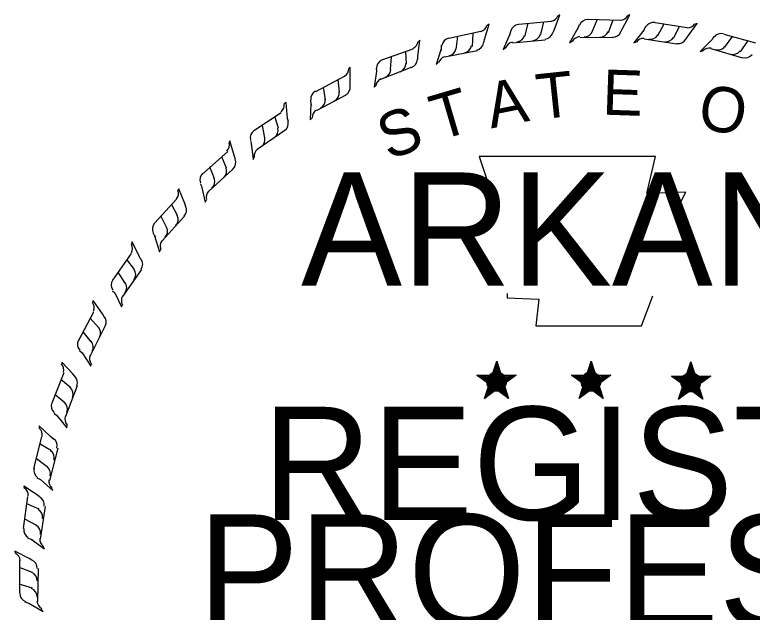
# Model space of a CAD drawing. Extents: x -1063117.8 to -1063083.7, y -253323.4 to -253301.6.
# Drawn here: x -1063093.123 to -1063091.9, y -253321.122 to -253320.131 of the extents above; entities that cross this region are included whole.
import ezdxf

# ---------------------------------------------------------------- set-up
doc = ezdxf.new("R2010")
doc.units = 0
doc.layers.add('Stamp-ChrisC', color=7, linetype='Continuous')

msp = doc.modelspace()

# ---------------------------------------------------------------- linework, layer by layer
at = {"layer": 'Stamp-ChrisC'}
for p, q in [((-1063092.2284, -253320.1569), (-1063092.2194, -253320.1314)), ((-1063092.2194, -253320.1314), (-1063092.2224, -253320.1337)), ((-1063092.1159, -253320.1554), (-1063092.1032, -253320.1314)), ((-1063092.1032, -253320.1314), (-1063092.1062, -253320.1329)), ((-1063092.2869, -253320.1472), (-1063092.2329, -253320.1419)), ((-1063092.2509, -253320.1644), (-1063092.2457, -253320.1434)), ((-1063092.1722, -253320.1389), (-1063092.1182, -253320.1404)), ((-1063092.1654, -253320.1599), (-1063092.1572, -253320.1397)), ((-1063092.1384, -253320.1607), (-1063092.1309, -253320.1397)), ((-1063092.3439, -253320.1727), (-1063092.3364, -253320.1472)), ((-1063092.3364, -253320.1472), (-1063092.3394, -253320.1494)), ((-1063092.2772, -253320.1674), (-1063092.2719, -253320.1457)), ((-1063092.1894, -253320.1539), (-1063092.2029, -253320.1779)), ((-1063092.1894, -253320.1539), (-1063092.1902, -253320.1562)), ((-1063092.1872, -253320.1479), (-1063092.1894, -253320.1539)), ((-1063092.1182, -253320.1599), (-1063092.1159, -253320.1554)), ((-1063092.0769, -253320.1509), (-1063092.0799, -253320.1569)), ((-1063092.0612, -253320.1442), (-1063092.0079, -253320.1524)), ((-1063092.0567, -253320.1659), (-1063092.0462, -253320.1464)), ((-1063092.0304, -253320.1704), (-1063092.0207, -253320.1509)), ((-1063092.0072, -253320.1682), (-1063091.9914, -253320.1457)), ((-1063091.9914, -253320.1457), (-1063091.9944, -253320.1472)), ((-1063092.4032, -253320.1704), (-1063092.3499, -253320.1584)), ((-1063092.3912, -253320.1892), (-1063092.3882, -253320.1667)), ((-1063092.3642, -253320.1839), (-1063092.3627, -253320.1622)), ((-1063092.3019, -253320.1637), (-1063092.3132, -253320.1892)), ((-1063092.3019, -253320.1637), (-1063092.3027, -253320.1659)), ((-1063092.3004, -253320.1577), (-1063092.3019, -253320.1637)), ((-1063092.2307, -253320.1614), (-1063092.2284, -253320.1569)), ((-1063092.0799, -253320.1569), (-1063092.0964, -253320.1779)), ((-1063092.0799, -253320.1569), (-1063092.0807, -253320.1584)), ((-1063092.0102, -253320.1719), (-1063092.0072, -253320.1682)), ((-1063091.9637, -253320.1674), (-1063091.9667, -253320.1727)), ((-1063091.9472, -253320.1637), (-1063091.8947, -253320.1779)), ((-1063091.9457, -253320.1854), (-1063091.9329, -253320.1674)), ((-1063092.4549, -253320.2004), (-1063092.4512, -253320.1734)), ((-1063092.4512, -253320.1734), (-1063092.4534, -253320.1764)), ((-1063092.3454, -253320.1779), (-1063092.3439, -253320.1727)), ((-1063092.2434, -253320.1734), (-1063092.2974, -253320.1787)), ((-1063092.2029, -253320.1779), (-1063092.1984, -253320.1749)), ((-1063092.1309, -253320.1697), (-1063092.1857, -253320.1689)), ((-1063092.0964, -253320.1779), (-1063092.0919, -253320.1757)), ((-1063092.0252, -253320.1802), (-1063092.0792, -253320.1719)), ((-1063091.9667, -253320.1727), (-1063091.9862, -253320.1922)), ((-1063091.9667, -253320.1727), (-1063091.9682, -253320.1742)), ((-1063091.9194, -253320.1929), (-1063091.9067, -253320.1742)), ((-1063092.5142, -253320.2064), (-1063092.4624, -253320.1877)), ((-1063092.4737, -253320.2132), (-1063092.4744, -253320.1922)), ((-1063092.4159, -253320.1877), (-1063092.4242, -253320.2139)), ((-1063092.4159, -253320.1817), (-1063092.4159, -253320.1877)), ((-1063092.4159, -253320.1877), (-1063092.4159, -253320.1907)), ((-1063092.3559, -253320.1914), (-1063092.4099, -253320.2019)), ((-1063092.3132, -253320.1892), (-1063092.3087, -253320.1854)), ((-1063091.9862, -253320.1922), (-1063091.9809, -253320.1907)), ((-1063091.9157, -253320.2034), (-1063091.9682, -253320.1877)), ((-1063092.4999, -253320.2222), (-1063092.4984, -253320.2012)), ((-1063092.4549, -253320.2057), (-1063092.4549, -253320.2004)), ((-1063092.4242, -253320.2139), (-1063092.4204, -253320.2102)), ((-1063092.5667, -253320.2184), (-1063092.5689, -253320.2207)), ((-1063092.5667, -253320.2447), (-1063092.5667, -253320.2184)), ((-1063092.5232, -253320.2252), (-1063092.5269, -253320.2514)), ((-1063092.5239, -253320.2199), (-1063092.5232, -253320.2252)), ((-1063092.5232, -253320.2252), (-1063092.5239, -253320.2282)), ((-1063092.4647, -253320.2184), (-1063092.5164, -253320.2387)), ((-1063092.6237, -253320.2589), (-1063092.5764, -253320.2334)), ((-1063092.5847, -253320.2597), (-1063092.5869, -253320.2387)), ((-1063092.6079, -253320.2724), (-1063092.6109, -253320.2514)), ((-1063092.5667, -253320.2499), (-1063092.5667, -253320.2447)), ((-1063092.5269, -253320.2514), (-1063092.5239, -253320.2484)), ((-1063092.5742, -253320.2649), (-1063092.6222, -253320.2904)), ((-1063092.6732, -253320.2769), (-1063092.6762, -253320.2792)), ((-1063092.6709, -253320.3032), (-1063092.6732, -253320.2769)), ((-1063092.6327, -253320.2732), (-1063092.6319, -253320.2792)), ((-1063092.6319, -253320.2792), (-1063092.6334, -253320.3054)), ((-1063092.6319, -253320.2792), (-1063092.6312, -253320.2814)), ((-1063092.7264, -253320.3234), (-1063092.6814, -253320.2934)), ((-1063092.6859, -253320.3197), (-1063092.6919, -253320.3002)), ((-1063092.6334, -253320.3054), (-1063092.6297, -253320.3024)), ((-1063092.7084, -253320.3354), (-1063092.7122, -253320.3152)), ((-1063092.6694, -253320.3084), (-1063092.6709, -253320.3032)), ((-1063092.6754, -253320.3234), (-1063092.7212, -253320.3549)), ((-1063092.7662, -253320.3407), (-1063092.7677, -253320.3437)), ((-1063092.7587, -253320.3662), (-1063092.7662, -253320.3407)), ((-1063092.7324, -253320.3399), (-1063092.7309, -253320.3444)), ((-1063092.7309, -253320.3444), (-1063092.7279, -253320.3714)), ((-1063092.7309, -253320.3444), (-1063092.7309, -253320.3474)), ((-1063092.8104, -253320.3939), (-1063092.7699, -253320.3579)), ((-1063092.7722, -253320.3857), (-1063092.7797, -253320.3669)), ((-1063092.7572, -253320.3707), (-1063092.7587, -253320.3662)), ((-1063092.7279, -253320.3714), (-1063092.7257, -253320.3669)), ((-1063092.7617, -253320.3872), (-1063092.8014, -253320.4239)), ((-1063092.7917, -253320.4037), (-1063092.7999, -253320.3834)), ((-1063092.8157, -253320.4112), (-1063092.8134, -253320.4157)), ((-1063092.8509, -253320.4202), (-1063092.8524, -253320.4224)), ((-1063092.8412, -253320.4442), (-1063092.8509, -253320.4202)), ((-1063092.8134, -253320.4157), (-1063092.8074, -253320.4419)), ((-1063092.8134, -253320.4157), (-1063092.8127, -253320.4179)), ((-1063092.8907, -253320.4764), (-1063092.8547, -253320.4374)), ((-1063092.8532, -253320.4644), (-1063092.8629, -253320.4464)), ((-1063092.8397, -253320.4494), (-1063092.8412, -253320.4442)), ((-1063092.8074, -253320.4419), (-1063092.8052, -253320.4382)), ((-1063092.8712, -253320.4847), (-1063092.8802, -253320.4659)), ((-1063092.8419, -253320.4652), (-1063092.8787, -253320.5064)), ((-1063092.8937, -253320.4937), (-1063092.8914, -253320.4982)), ((-1063092.8914, -253320.4982), (-1063092.8832, -253320.5244)), ((-1063092.8914, -253320.4982), (-1063092.8899, -253320.5004)), ((-1063092.9282, -253320.5079), (-1063092.9297, -253320.5117)), ((-1063092.9162, -253320.5327), (-1063092.9282, -253320.5079)), ((-1063092.8832, -253320.5244), (-1063092.8809, -253320.5199)), ((-1063092.9604, -253320.5717), (-1063092.9297, -253320.5274)), ((-1063092.9139, -253320.5372), (-1063092.9162, -253320.5327)), ((-1063092.9244, -253320.5537), (-1063092.9372, -253320.5372)), ((-1063092.9402, -253320.5762), (-1063092.9514, -253320.5582)), ((-1063092.9132, -253320.5537), (-1063092.9447, -253320.5987)), ((-1063092.9612, -253320.5889), (-1063092.9574, -253320.5927)), ((-1063092.9574, -253320.5927), (-1063092.9462, -253320.6159)), ((-1063092.9574, -253320.5927), (-1063092.9559, -253320.5949)), ((-1063092.9934, -253320.6054), (-1063092.9942, -253320.6092)), ((-1063092.9777, -253320.6272), (-1063092.9934, -253320.6054)), ((-1063092.9462, -253320.6159), (-1063092.9447, -253320.6114)), ((-1063093.0174, -253320.6722), (-1063092.9919, -253320.6242)), ((-1063092.9754, -253320.6309), (-1063092.9777, -253320.6272)), ((-1063092.9844, -253320.6497), (-1063092.9979, -253320.6347)), ((-1063092.9964, -253320.6737), (-1063093.0099, -253320.6572)), ((-1063092.9732, -253320.6474), (-1063092.9979, -253320.6969)), ((-1063093.0159, -253320.6879), (-1063093.0114, -253320.6917)), ((-1063093.0114, -253320.6917), (-1063092.9972, -253320.7142)), ((-1063093.0114, -253320.6917), (-1063093.0099, -253320.6939)), ((-1063092.3237, -253320.7059), (-1063092.3289, -253320.7284)), ((-1063092.3237, -253320.7059), (-1063092.3274, -253320.7292)), ((-1063092.3237, -253320.7059), (-1063092.3252, -253320.7292)), ((-1063092.3237, -253320.7397), (-1063092.3237, -253320.7059)), ((-1063092.3237, -253320.7059), (-1063092.3177, -253320.7292)), ((-1063092.3237, -253320.7059), (-1063092.3192, -253320.7292)), ((-1063092.3237, -253320.7059), (-1063092.3214, -253320.7292)), ((-1063092.1669, -253320.7059), (-1063092.1729, -253320.7284)), ((-1063092.1669, -253320.7059), (-1063092.1707, -253320.7292)), ((-1063092.1669, -253320.7059), (-1063092.1692, -253320.7292)), ((-1063092.1669, -253320.7397), (-1063092.1669, -253320.7059)), ((-1063092.1669, -253320.7059), (-1063092.1609, -253320.7292)), ((-1063092.1669, -253320.7059), (-1063092.1624, -253320.7292)), ((-1063092.1669, -253320.7059), (-1063092.1654, -253320.7292)), ((-1063092.0019, -253320.7067), (-1063092.0072, -253320.7299)), ((-1063092.0019, -253320.7067), (-1063092.0057, -253320.7299)), ((-1063092.0019, -253320.7067), (-1063092.0034, -253320.7299)), ((-1063092.0019, -253320.7412), (-1063092.0019, -253320.7067)), ((-1063092.0019, -253320.7067), (-1063091.9952, -253320.7299)), ((-1063092.0019, -253320.7067), (-1063091.9967, -253320.7299)), ((-1063092.0019, -253320.7067), (-1063091.9997, -253320.7299)), ((-1063093.0272, -253320.7262), (-1063093.0452, -253320.7074)), ((-1063093.0452, -253320.7074), (-1063093.0452, -253320.7104)), ((-1063092.9972, -253320.7142), (-1063092.9957, -253320.7097)), ((-1063093.0609, -253320.7749), (-1063093.0414, -253320.7247)), ((-1063093.0242, -253320.7299), (-1063093.0272, -253320.7262)), ((-1063092.3567, -253320.7292), (-1063092.3237, -253320.7397)), ((-1063092.3567, -253320.7292), (-1063092.3327, -253320.7322)), ((-1063092.3567, -253320.7292), (-1063092.3327, -253320.7337)), ((-1063092.3567, -253320.7292), (-1063092.3334, -253320.7352)), ((-1063092.3567, -253320.7292), (-1063092.3342, -253320.7389)), ((-1063092.3567, -253320.7292), (-1063092.3342, -253320.7412)), ((-1063092.3567, -253320.7292), (-1063092.3342, -253320.7434)), ((-1063092.2914, -253320.7292), (-1063092.3237, -253320.7397)), ((-1063092.2914, -253320.7292), (-1063092.3199, -253320.7314)), ((-1063092.2914, -253320.7292), (-1063092.3177, -253320.7344)), ((-1063092.2914, -253320.7292), (-1063092.3177, -253320.7359)), ((-1063092.2914, -253320.7292), (-1063092.3117, -253320.7382)), ((-1063092.2914, -253320.7292), (-1063092.3102, -253320.7389)), ((-1063092.2914, -253320.7292), (-1063092.3087, -253320.7404)), ((-1063092.1999, -253320.7292), (-1063092.1669, -253320.7397)), ((-1063092.1999, -253320.7292), (-1063092.1759, -253320.7322)), ((-1063092.1999, -253320.7292), (-1063092.1767, -253320.7337)), ((-1063092.1999, -253320.7292), (-1063092.1767, -253320.7352)), ((-1063092.1999, -253320.7292), (-1063092.1774, -253320.7389)), ((-1063092.1999, -253320.7292), (-1063092.1782, -253320.7412)), ((-1063092.1999, -253320.7292), (-1063092.1782, -253320.7434)), ((-1063092.1347, -253320.7292), (-1063092.1669, -253320.7397)), ((-1063092.1347, -253320.7292), (-1063092.1632, -253320.7314)), ((-1063092.1347, -253320.7292), (-1063092.1617, -253320.7344)), ((-1063092.1347, -253320.7292), (-1063092.1617, -253320.7359)), ((-1063092.1347, -253320.7292), (-1063092.1557, -253320.7382)), ((-1063092.1347, -253320.7292), (-1063092.1542, -253320.7389)), ((-1063092.1347, -253320.7292), (-1063092.1527, -253320.7404)), ((-1063092.0342, -253320.7307), (-1063092.0019, -253320.7412)), ((-1063092.0342, -253320.7307), (-1063092.0102, -253320.7329)), ((-1063092.0342, -253320.7307), (-1063092.0102, -253320.7344)), ((-1063092.0342, -253320.7307), (-1063092.0117, -253320.7367)), ((-1063092.0342, -253320.7307), (-1063092.0117, -253320.7397)), ((-1063092.0342, -253320.7307), (-1063092.0124, -253320.7419)), ((-1063092.0342, -253320.7307), (-1063092.0124, -253320.7442)), ((-1063091.9689, -253320.7307), (-1063092.0019, -253320.7412)), ((-1063091.9689, -253320.7307), (-1063091.9982, -253320.7329)), ((-1063091.9689, -253320.7307), (-1063091.9959, -253320.7352)), ((-1063091.9689, -253320.7307), (-1063091.9959, -253320.7367)), ((-1063091.9689, -253320.7307), (-1063091.9899, -253320.7389)), ((-1063091.9689, -253320.7307), (-1063091.9884, -253320.7404)), ((-1063091.9689, -253320.7307), (-1063091.9869, -253320.7412)), ((-1063093.0302, -253320.7502), (-1063093.0467, -253320.7359)), ((-1063092.3439, -253320.7674), (-1063092.3237, -253320.7397)), ((-1063092.3439, -253320.7674), (-1063092.3334, -253320.7419)), ((-1063092.3042, -253320.7674), (-1063092.3237, -253320.7397)), ((-1063092.3042, -253320.7674), (-1063092.3169, -253320.7404)), ((-1063092.3042, -253320.7674), (-1063092.3147, -253320.7404)), ((-1063092.1872, -253320.7674), (-1063092.1669, -253320.7397)), ((-1063092.1872, -253320.7674), (-1063092.1767, -253320.7419)), ((-1063092.1474, -253320.7674), (-1063092.1669, -253320.7397)), ((-1063092.1474, -253320.7674), (-1063092.1602, -253320.7404)), ((-1063092.1474, -253320.7674), (-1063092.1579, -253320.7404)), ((-1063092.0222, -253320.7689), (-1063092.0019, -253320.7412)), ((-1063092.0222, -253320.7689), (-1063092.0117, -253320.7434)), ((-1063091.9817, -253320.7689), (-1063092.0019, -253320.7412)), ((-1063091.9817, -253320.7689), (-1063091.9944, -253320.7419)), ((-1063091.9817, -253320.7689), (-1063091.9922, -253320.7412)), ((-1063093.0197, -253320.7464), (-1063093.0392, -253320.7974)), ((-1063092.3439, -253320.7674), (-1063092.3319, -253320.7449)), ((-1063092.3439, -253320.7674), (-1063092.3304, -253320.7457)), ((-1063092.3439, -253320.7674), (-1063092.3237, -253320.7472)), ((-1063092.3439, -253320.7674), (-1063092.3274, -253320.7479)), ((-1063092.3439, -253320.7674), (-1063092.3237, -253320.7502)), ((-1063092.3042, -253320.7674), (-1063092.3237, -253320.7479)), ((-1063092.3042, -253320.7674), (-1063092.3237, -253320.7502)), ((-1063092.3042, -253320.7674), (-1063092.3207, -253320.7479)), ((-1063092.3042, -253320.7674), (-1063092.3177, -253320.7449)), ((-1063092.1872, -253320.7674), (-1063092.1759, -253320.7449)), ((-1063092.1872, -253320.7674), (-1063092.1737, -253320.7457)), ((-1063092.1872, -253320.7674), (-1063092.1677, -253320.7472)), ((-1063092.1872, -253320.7674), (-1063092.1707, -253320.7479)), ((-1063092.1872, -253320.7674), (-1063092.1669, -253320.7502)), ((-1063092.1474, -253320.7674), (-1063092.1677, -253320.7479)), ((-1063092.1474, -253320.7674), (-1063092.1677, -253320.7502)), ((-1063092.1474, -253320.7674), (-1063092.1639, -253320.7479)), ((-1063092.1474, -253320.7674), (-1063092.1609, -253320.7449)), ((-1063092.0222, -253320.7689), (-1063092.0102, -253320.7457)), ((-1063092.0222, -253320.7689), (-1063092.0079, -253320.7464)), ((-1063092.0222, -253320.7689), (-1063092.0019, -253320.7487)), ((-1063092.0222, -253320.7689), (-1063092.0057, -253320.7494)), ((-1063092.0222, -253320.7689), (-1063092.0012, -253320.7509)), ((-1063091.9817, -253320.7689), (-1063092.0019, -253320.7487)), ((-1063091.9817, -253320.7689), (-1063092.0019, -253320.7517)), ((-1063091.9817, -253320.7689), (-1063091.9982, -253320.7494)), ((-1063091.9817, -253320.7689), (-1063091.9952, -253320.7457)), ((-1063093.0399, -253320.7749), (-1063093.0564, -253320.7614)), ((-1063093.0579, -253320.7922), (-1063093.0534, -253320.7959)), ((-1063093.0534, -253320.7959), (-1063093.0369, -253320.8162)), ((-1063093.0534, -253320.7959), (-1063093.0519, -253320.7974)), ((-1063093.0632, -253320.8312), (-1063093.0827, -253320.8132)), ((-1063093.0827, -253320.8132), (-1063093.0827, -253320.8169)), ((-1063093.0369, -253320.8162), (-1063093.0362, -253320.8117)), ((-1063093.0917, -253320.8837), (-1063093.0782, -253320.8312)), ((-1063093.0587, -253320.8349), (-1063093.0632, -253320.8312)), ((-1063093.0624, -253320.8544), (-1063093.0812, -253320.8432)), ((-1063093.0519, -253320.8499), (-1063093.0654, -253320.9039)), ((-1063093.0692, -253320.8807), (-1063093.0872, -253320.8679)), ((-1063093.0864, -253320.8994), (-1063093.0804, -253320.9017)), ((-1063093.0804, -253320.9017), (-1063093.0602, -253320.9204)), ((-1063093.0804, -253320.9017), (-1063093.0789, -253320.9039)), ((-1063093.0857, -253320.9279), (-1063093.1082, -253320.9129)), ((-1063093.1082, -253320.9129), (-1063093.1074, -253320.9167)), ((-1063093.0602, -253320.9204), (-1063093.0624, -253320.9159)), ((-1063093.1089, -253320.9834), (-1063093.1014, -253320.9302)), ((-1063093.0819, -253320.9309), (-1063093.0857, -253320.9279)), ((-1063093.0827, -253320.9512), (-1063093.1029, -253320.9422)), ((-1063093.0729, -253320.9467), (-1063093.0812, -253321.0007)), ((-1063093.0864, -253320.9782), (-1063093.1067, -253320.9677)), ((-1063093.1014, -253320.9992), (-1063093.0962, -253321.0007)), ((-1063093.0962, -253321.0007), (-1063093.0737, -253321.0172)), ((-1063093.0962, -253321.0007), (-1063093.0939, -253321.0022)), ((-1063093.0992, -253321.0329), (-1063093.1232, -253321.0209)), ((-1063093.1232, -253321.0209), (-1063093.1217, -253321.0239)), ((-1063093.0737, -253321.0172), (-1063093.0767, -253321.0127)), ((-1063093.1149, -253321.0899), (-1063093.1149, -253321.0359)), ((-1063093.0947, -253321.0359), (-1063093.0992, -253321.0329)), ((-1063093.0939, -253321.0562), (-1063093.1142, -253321.0487)), ((-1063093.0842, -253321.0494), (-1063093.0857, -253321.1042)), ((-1063093.0939, -253321.0824), (-1063093.1157, -253321.0757)), ((-1063093.1067, -253321.1049), (-1063093.0999, -253321.1072)), ((-1063093.0999, -253321.1072), (-1063093.0759, -253321.1207)), ((-1063093.0999, -253321.1072), (-1063093.0977, -253321.1079)), ((-1063093.0759, -253321.1207), (-1063093.0797, -253321.1169))]:
    msp.add_line(p, q, dxfattribs=at)
for points in [[(-1063092.3529, -253320.3662), (-1063092.3274, -253320.4434)], [(-1063092.0237, -253320.4524), (-1063092.0102, -253320.4254), (-1063092.0747, -253320.4277), (-1063092.0604, -253320.3662), (-1063092.3529, -253320.3662)], [(-1063092.3064, -253320.5934), (-1063092.3064, -253320.6009), (-1063092.2539, -253320.6032), (-1063092.2592, -253320.6474), (-1063092.0837, -253320.6474), (-1063092.0649, -253320.5972)], [(-1063092.3237, -253320.7059), (-1063092.3042, -253320.7674), (-1063092.3567, -253320.7292), (-1063092.2914, -253320.7292), (-1063092.3439, -253320.7674), (-1063092.3237, -253320.7059)], [(-1063092.1669, -253320.7059), (-1063092.1474, -253320.7674), (-1063092.1999, -253320.7292), (-1063092.1347, -253320.7292), (-1063092.1872, -253320.7674), (-1063092.1669, -253320.7059)], [(-1063092.0019, -253320.7067), (-1063091.9817, -253320.7689), (-1063092.0342, -253320.7307), (-1063091.9689, -253320.7307), (-1063092.0222, -253320.7689), (-1063092.0019, -253320.7067)]]:
    msp.add_lwpolyline(points, dxfattribs=at)
for centre, radius in [((-1063092.3241, -253320.7396), 0.0161), ((-1063092.3241, -253320.7396), 0.0146), ((-1063092.3241, -253320.7396), 0.0136), ((-1063092.3241, -253320.7396), 0.0124), ((-1063092.3241, -253320.7396), 0.0109), ((-1063092.3241, -253320.7396), 0.0101), ((-1063092.3241, -253320.7396), 0.00929), ((-1063092.1676, -253320.7396), 0.0161), ((-1063092.1676, -253320.7396), 0.0146), ((-1063092.1676, -253320.7396), 0.0136), ((-1063092.1676, -253320.7396), 0.0124), ((-1063092.1676, -253320.7396), 0.0109), ((-1063092.1676, -253320.7396), 0.0101), ((-1063092.1676, -253320.7396), 0.00929), ((-1063092.0019, -253320.7407), 0.0161), ((-1063092.0019, -253320.7407), 0.0146), ((-1063092.0019, -253320.7407), 0.0136), ((-1063092.0019, -253320.7407), 0.0124), ((-1063092.0019, -253320.7407), 0.0109), ((-1063092.0019, -253320.7407), 0.0101), ((-1063092.3241, -253320.7396), 0.008), ((-1063092.3241, -253320.7396), 0.00701), ((-1063092.3241, -253320.7396), 0.00583), ((-1063092.3241, -253320.7396), 0.00464), ((-1063092.3241, -253320.7396), 0.00346), ((-1063092.3241, -253320.7396), 0.00278), ((-1063092.3241, -253320.7396), 0.00135), ((-1063092.1676, -253320.7396), 0.008), ((-1063092.1676, -253320.7396), 0.00701), ((-1063092.1676, -253320.7396), 0.00583), ((-1063092.1676, -253320.7396), 0.00464), ((-1063092.1676, -253320.7396), 0.00346), ((-1063092.1676, -253320.7396), 0.00278), ((-1063092.1676, -253320.7396), 0.00135), ((-1063092.0019, -253320.7407), 0.00929), ((-1063092.0019, -253320.7407), 0.008), ((-1063092.0019, -253320.7407), 0.00701), ((-1063092.0019, -253320.7407), 0.00583), ((-1063092.0019, -253320.7407), 0.00464), ((-1063092.0019, -253320.7407), 0.00346), ((-1063092.0019, -253320.7407), 0.00278), ((-1063092.0019, -253320.7407), 0.00135)]:
    msp.add_circle(centre, radius, dxfattribs=at)
for centre, start, end in [((-1063092.236, -253320.1277), 279.9249, 338.7128), ((-1063092.173, -253320.1542), 89.1628, 157.5368), ((-1063092.1194, -253320.1257), 273.4236, 332.2115), ((-1063092.3543, -253320.1451), 286.2701, 345.0579), ((-1063092.2861, -253320.1621), 95.6641, 164.0381), ((-1063092.064, -253320.1591), 81.4231, 149.797), ((-1063092.007, -253320.1381), 265.6839, 324.4717), ((-1063092.2919, -253320.1618), 275.6641, 344.0381), ((-1063092.2655, -253320.1593), 275.6641, 344.0381), ((-1063092.2451, -253320.1572), 275.6641, 344.0381), ((-1063092.1854, -253320.1825), 93.4236, 152.2115), ((-1063092.1787, -253320.1532), 269.1628, 337.5368), ((-1063092.1523, -253320.1537), 269.1628, 337.5368), ((-1063092.1318, -253320.154), 269.1628, 337.5368), ((-1063092.0695, -253320.1574), 261.4231, 329.797), ((-1063091.9517, -253320.1774), 73.9909, 142.3649), ((-1063092.4689, -253320.1739), 294.8371, 353.6249), ((-1063092.4002, -253320.1849), 102.0093, 170.3833), ((-1063092.3601, -253320.1755), 282.0093, 350.3833), ((-1063092.2952, -253320.1916), 99.9249, 158.7128), ((-1063092.0801, -253320.1855), 85.6839, 144.4717), ((-1063092.0434, -253320.1614), 261.4231, 329.797), ((-1063092.0231, -253320.1644), 261.4231, 329.797), ((-1063092.406, -253320.1852), 282.0093, 350.3833), ((-1063092.3801, -253320.1798), 282.0093, 350.3833), ((-1063091.9711, -253320.2015), 78.2517, 137.0395), ((-1063091.957, -253320.175), 253.9909, 322.3649), ((-1063091.9316, -253320.1824), 253.9909, 322.3649), ((-1063092.4702, -253320.2048), 290.5763, 358.9503), ((-1063092.4061, -253320.2152), 106.2701, 165.0579), ((-1063091.9118, -253320.188), 253.9909, 322.3649), ((-1063092.5085, -253320.2201), 110.5763, 178.9503), ((-1063092.4894, -253320.2121), 290.5763, 358.9503), ((-1063092.584, -253320.2205), 301.9545, 0.7423), ((-1063092.5142, -253320.2213), 290.5763, 358.9503), ((-1063092.5097, -253320.251), 114.8371, 173.6249), ((-1063092.5814, -253320.2513), 297.6937, 6.0677), ((-1063092.6176, -253320.2712), 117.6937, 186.0677), ((-1063092.5996, -253320.2609), 297.6937, 6.0677), ((-1063092.623, -253320.2731), 297.6937, 6.0677), ((-1063092.6908, -253320.281), 309.1135, 7.9014), ((-1063092.615, -253320.302), 121.9545, 180.7423), ((-1063092.6843, -253320.3112), 304.8528, 13.2267), ((-1063092.7177, -253320.3355), 124.8528, 193.2267), ((-1063092.7011, -253320.323), 304.8528, 13.2267), ((-1063092.7229, -253320.338), 304.8528, 13.2267), ((-1063092.782, -253320.3473), 316.8235, 15.6113), ((-1063092.7113, -253320.3657), 129.1135, 187.9014), ((-1063092.7715, -253320.3764), 312.5627, 20.9367), ((-1063092.7866, -253320.3903), 312.5627, 20.9367), ((-1063092.8014, -253320.4049), 132.5627, 200.9367), ((-1063092.8061, -253320.4081), 312.5627, 20.9367), ((-1063092.8664, -253320.4276), 322.2653, 21.0531), ((-1063092.7909, -253320.434), 136.8235, 195.6113), ((-1063092.8532, -253320.4556), 318.0045, 26.3785), ((-1063092.8669, -253320.4709), 318.0045, 26.3785), ((-1063092.8802, -253320.4868), 138.0045, 206.3785), ((-1063092.8847, -253320.4904), 318.0045, 26.3785), ((-1063092.8671, -253320.5148), 142.2653, 201.0531), ((-1063092.9426, -253320.5189), 329.9636, 28.7515), ((-1063092.9258, -253320.5449), 325.7028, 34.0768), ((-1063092.9374, -253320.5619), 325.7028, 34.0768), ((-1063092.9484, -253320.5794), 145.7028, 214.0768), ((-1063092.9523, -253320.5837), 325.7028, 34.0768), ((-1063093.0062, -253320.6171), 337.2243, 36.0121), ((-1063092.9316, -253320.6054), 149.9636, 208.7515), ((-1063092.9863, -253320.6408), 332.9635, 41.3375), ((-1063092.9956, -253320.6591), 332.9635, 41.3375), ((-1063093.0043, -253320.6779), 152.9635, 221.3375), ((-1063093.0077, -253320.6826), 332.9635, 41.3375), ((-1063092.9844, -253320.7015), 157.2243, 216.0121), ((-1063093.0565, -253320.7201), 343.6465, 42.4343), ((-1063093.034, -253320.7413), 339.3857, 47.7597), ((-1063093.0412, -253320.7605), 339.3857, 47.7597), ((-1063093.0478, -253320.7802), 159.3857, 227.7597), ((-1063093.0506, -253320.7853), 339.3857, 47.7597), ((-1063093.0254, -253320.8015), 163.6465, 222.4343), ((-1063093.0923, -253320.828), 350.445, 49.2329), ((-1063093.0675, -253320.8465), 346.1842, 54.5582), ((-1063093.0724, -253320.8664), 346.1842, 54.5582), ((-1063093.0766, -253320.8867), 166.1842, 234.5582), ((-1063093.0788, -253320.8921), 346.1842, 54.5582), ((-1063093.0518, -253320.9052), 170.445, 229.2329), ((-1063093.1156, -253320.9283), 356.646, 55.4338), ((-1063093.089, -253320.944), 352.3852, 60.7592), ((-1063093.0916, -253320.9644), 352.3852, 60.7592), ((-1063093.0936, -253320.985), 172.3852, 240.7592), ((-1063093.0952, -253320.9906), 352.3852, 60.7592), ((-1063093.067, -253321.0007), 176.646, 235.4338), ((-1063093.129, -253321.0371), 3.9474, 62.7352), ((-1063093.1006, -253321.0492), 359.6866, 68.0606), ((-1063093.1006, -253321.0698), 359.6866, 68.0606), ((-1063093.1009, -253321.0962), 359.6866, 68.0606), ((-1063093.1, -253321.0905), 179.6866, 248.0606), ((-1063093.0716, -253321.1027), 183.9474, 242.7352)]:
    msp.add_arc(centre, 0.0148, start, end, dxfattribs=at)

# ---------------------------------------------------------------- texts
for s, rotation, p in [('T', 6.0228, (-1063092.2544, -253320.3051)), ('E', 358.0732, (-1063092.1494, -253320.2969)), ('A', 11.2132, (-1063092.3332, -253320.3201)), ('T', 16.4036, (-1063092.4202, -253320.3404)), ('O', 350.4515, (-1063091.9927, -253320.3194)), ('S', 21.594, (-1063092.5027, -253320.3734))]:
    msp.add_text(s, height=0.075, rotation=rotation, dxfattribs=at).set_placement(p)
for s, height, p in [('ARKANSAS', 0.1875, (-1063092.6482, -253320.5804)), ('REGISTERED', 0.1875, (-1063092.7119, -253320.9689)), ('PROFESSIONAL', 0.187497, (-1063092.8192, -253321.1474))]:
    msp.add_text(s, height=height, dxfattribs=at).set_placement(p)

doc.saveas('drawing.dxf')
